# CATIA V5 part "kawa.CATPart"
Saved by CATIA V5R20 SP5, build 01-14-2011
Part number: 卡瓦
Bounding box of the stored display mesh (mm): x -40 to 90, y -40 to 16, z 0 to 100
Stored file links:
  E:\180522132\3.8卡瓦\kawa.CATPart
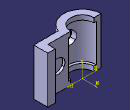
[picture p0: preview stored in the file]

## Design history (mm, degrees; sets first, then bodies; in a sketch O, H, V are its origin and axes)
Body1 (main body)
  Sketch1 on xy-plane, origin (0, 0, 0), H (1, 0, 0), V (0, 1, 0)
    arc A1 centre (0, 0) radius 25 from (-25, 0) to (25, 0) ccw
    arc A2 centre (0, 0) radius 40 from (-40, 0) to (37.47, -14) ccw
    point P1 (-40, 0)
    line L1 (-40, 0) -> (-25, 0)
    line L2 (74, 0) -> (74, 16)
    line L3 (74, 16) -> (90, 16)
    line L4 (90, 16) -> (90, -14)
    line L5 (90, -14) -> (37.47, -14)
    point P8 (25, 0)
    line L6 (25, 0) -> (74, 0)
    length L4 = 30
    length L3 = 16
    length L2 = 16
    distance V L2 = 74
    length L1 = 15
    distance O A2 = 40
    coincidence: P1 H, L1 P8, L1 L6
    horizontal: L1 H, L3 H, L5 H, L6 H
    vertical: L2 V, L4 V
  Pad1: profile Sketch1, direction (0, 0, 1), length 100
  Sketch2 on xy-plane, origin (0, 0, 0), H (1, 0, 0), V (0, 1, 0)
  Sketch3 on zx-plane, origin (0, 0, 0), H (-1, 0, 0), V (0, 0, 1)
    point P1 (0, 90.3391)
    line L1 (0, 90.3391) -> (30.2288, 90.3391)
    line L2 (30.2288, 90.3391) -> (30.2288, 10.3991)
    line L3 (30.2288, 10.3991) -> (0, 10.3991)
    line L4 (0, 10.3991) -> (0, 90.3391)
    coincidence: P1 V
    horizontal: L1 H, L3 H
    vertical: L2 V, L4 V
  Sketch4 on xy-plane, origin (0, 0, 0), H (1, 0, 0), V (0, 1, 0)
  Sketch5 on yz-plane, origin (0, 0, 0), H (0, 1, 0), V (0, 0, 1)
  Sketch6 on {plane type Tangent, Support face of Pad1 from Sketch1.A1, RefPoint {point type OnSurface, Support face of Pad1 from Sketch1.A1, RefPoint {point stored without definition}, Length 0, Direction (0, 0, -1000)}}, origin (0.554, -24.9939, 59.1277), H (0.9998, 0.0222, 0), V (0, 0, 1)
    point P1 (0, 0)
  Hole1: placed by Sketch6, at (0.554, -24.9939, 59.1277) direction (0.0222, -0.9998, 0), diameter 30, through (limit type 3)
  Sketch7 on zx-plane, origin (0, 0, 0), H (-1, 0, 0), V (0, 0, 1)
  Groove1: profile Sketch3, axis Sketch3.L4, angle 360
  Sketch8 on face of Pad1 from Sketch1.L6, origin (53.0496, 0, 50.428), H (1, 0, 0), V (0, 0, -1)
    point P1 (0, 0)
  Hole2: placed by Sketch8, at (53.0496, 0, 50.428) direction (0, 1, 0), diameter 10, through (limit type 3)
  Sketch9 on face of Pad1 from Sketch1.L6, origin (52.1918, 0, 48.7202), H (1, 0, 0), V (0, 0, -1)
    point P1 (0, 0)
  Hole3: placed by Sketch9, at (52.1918, 0, 48.7202) direction (0, -1, 0), diameter 30, depth 5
